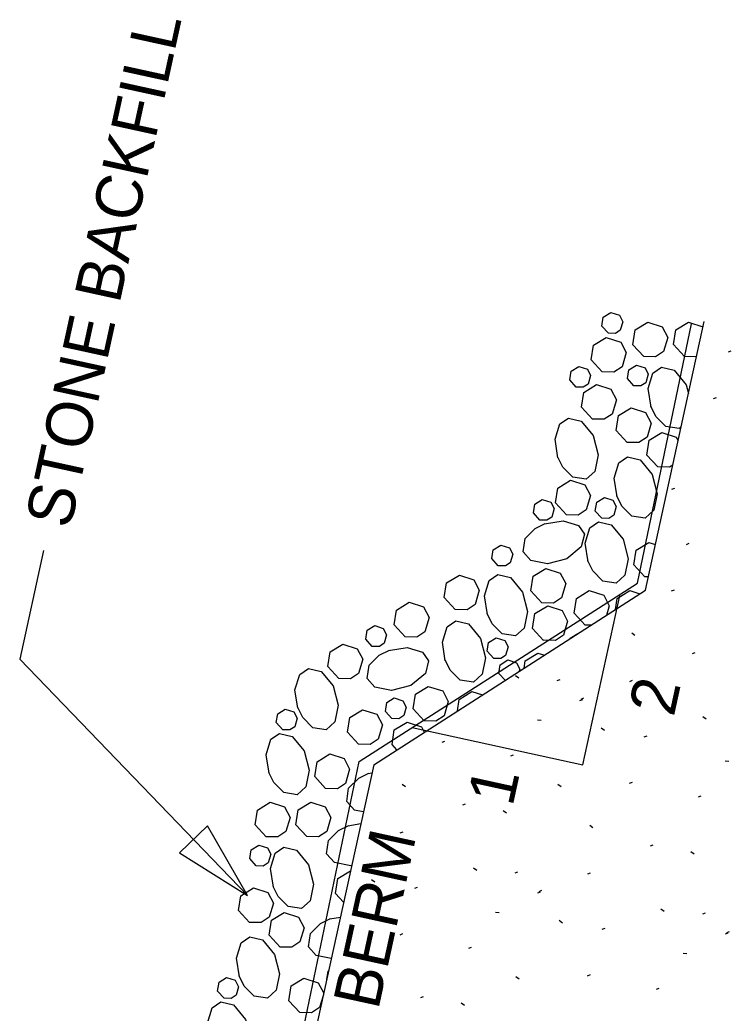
# Model space of a CAD drawing. Extents: x 2126110 to 2128246, y 1804858 to 1811658.
# Drawn here: x 2126594.3 to 2126671.1, y 1805662.4 to 1805769.7 of the extents above; entities that cross this region are included whole.
import ezdxf

# ---------------------------------------------------------------- set-up
doc = ezdxf.new("R2010")
doc.units = 0
doc.layers.add('1', color=7, linetype='Continuous')

msp = doc.modelspace()

# ---------------------------------------------------------------- linework, layer by layer
at = {"layer": '1'}
for p, q in [((2126661.04, 1805708.83), (2126666.87, 1805736.83)), ((2126661.88, 1805708.05), (2126668.22, 1805737.07)), ((2126670.84, 1805733.79), (2126671.14, 1805733.91)), ((2126669.25, 1805728.77), (2126669.55, 1805728.89)), ((2126664.74, 1805718.99), (2126665.04, 1805719.1)), ((2126666.3, 1805713.01), (2126666.6, 1805713.13)), ((2126596.85, 1805712.34), (2126594.29, 1805700.61)), ((2126662.19, 1805709.49), (2126661.81, 1805709.5)), ((2126630.94, 1805689.55), (2126661.04, 1805708.83)), ((2126632.52, 1805689.22), (2126661.88, 1805708.05)), ((2126655.12, 1805689.19), (2126659.15, 1805707.63)), ((2126664.71, 1805707.99), (2126665.01, 1805708.11)), ((2126655.99, 1805704.28), (2126655.37, 1805704.29)), ((2126660.75, 1805703.18), (2126660.4, 1805703.43)), ((2126666.95, 1805701.22), (2126667.25, 1805701.33)), ((2126618.9, 1805675.08), (2126594.29, 1805700.61)), ((2126648.19, 1805698.56), (2126647.84, 1805698.82)), ((2126652.35, 1805698.31), (2126652.65, 1805698.43)), ((2126660.2, 1805698.21), (2126660.5, 1805698.33)), ((2126654.94, 1805696.31), (2126655.24, 1805696.43)), ((2126654.8, 1805696.16), (2126655.1, 1805696.27)), ((2126668.46, 1805694.13), (2126668.1, 1805694.39)), ((2126636.67, 1805693.22), (2126655.12, 1805689.19)), ((2126650.21, 1805694.06), (2126650.61, 1805694.02)), ((2126657.46, 1805692.9), (2126657.11, 1805693.15)), ((2126661.76, 1805692.24), (2126662.06, 1805692.35)), ((2126639.91, 1805691.64), (2126640.21, 1805691.76)), ((2126647.35, 1805690.19), (2126647.64, 1805690.3)), ((2126624.81, 1805660.2), (2126630.94, 1805689.55)), ((2126632.52, 1805689.22), (2126626.17, 1805660.17)), ((2126670.48, 1805689.63), (2126670.88, 1805689.59)), ((2126631.91, 1805688.27), (2126632.33, 1805688.34)), ((2126635.95, 1805686.82), (2126635.6, 1805687.08)), ((2126652.77, 1805686.83), (2126652.41, 1805687.09)), ((2126660.17, 1805687.21), (2126660.47, 1805687.33)), ((2126667.61, 1805685.76), (2126667.91, 1805685.87)), ((2126642.15, 1805684.87), (2126642.45, 1805684.98)), ((2126646.87, 1805683.98), (2126646.52, 1805684.24)), ((2126629.74, 1805682.63), (2126631.13, 1805682.86)), ((2126656.21, 1805682.4), (2126655.86, 1805682.66)), ((2126635.39, 1805681.86), (2126635.69, 1805681.98)), ((2126662.41, 1805680.44), (2126662.71, 1805680.55)), ((2126667.13, 1805679.56), (2126666.78, 1805679.81)), ((2126643.65, 1805677.78), (2126643.3, 1805678.04)), ((2126647.81, 1805677.53), (2126648.11, 1805677.65)), ((2126655.66, 1805677.43), (2126655.96, 1805677.55)), ((2126632.66, 1805676.54), (2126632.3, 1805676.8)), ((2126636.96, 1805675.89), (2126637.26, 1805676)), ((2126650.26, 1805675.38), (2126650.56, 1805675.5)), ((2126650.4, 1805675.53), (2126650.7, 1805675.65)), ((2126627.79, 1805672.56), (2126628.92, 1805672.75)), ((2126645.67, 1805673.28), (2126646.07, 1805673.24)), ((2126663.91, 1805673.35), (2126663.56, 1805673.61)), ((2126668.07, 1805673.1), (2126668.37, 1805673.22)), ((2126652.92, 1805672.12), (2126652.57, 1805672.38)), ((2126635.37, 1805670.86), (2126635.67, 1805670.98)), ((2126657.22, 1805671.46), (2126657.52, 1805671.57)), ((2126670.53, 1805670.95), (2126670.82, 1805671.07)), ((2126670.66, 1805671.1), (2126670.96, 1805671.22)), ((2126642.81, 1805669.41), (2126643.1, 1805669.52)), ((2126665.94, 1805668.85), (2126666.34, 1805668.81)), ((2126631.41, 1805666.05), (2126631.06, 1805666.31)), ((2126648.23, 1805666.05), (2126647.87, 1805666.31)), ((2126655.63, 1805666.43), (2126655.93, 1805666.55)), ((2126637.61, 1805664.09), (2126637.91, 1805664.2)), ((2126663.07, 1805664.98), (2126663.37, 1805665.1)), ((2126642.33, 1805663.21), (2126641.98, 1805663.46))]:
    msp.add_line(p, q, dxfattribs=at)
for points in [[(2126657.88, 1805735.82), (2126657.17, 1805736.59), (2126657.32, 1805737.55), (2126658.14, 1805738.05), (2126659.07, 1805737.75), (2126659.43, 1805737.06), (2126659.16, 1805736.14), (2126658.64, 1805735.8), (2126657.88, 1805735.82)], [(2126661.71, 1805733.29), (2126660.52, 1805734.58), (2126660.78, 1805736.17), (2126662.15, 1805737.01), (2126663.7, 1805736.51), (2126664.3, 1805735.36), (2126663.85, 1805733.83), (2126662.98, 1805733.26), (2126661.71, 1805733.29)], [(2126666.11, 1805733.3), (2126664.92, 1805734.59), (2126665.17, 1805736.18), (2126666.55, 1805737.02), (2126668.1, 1805736.52), (2126668.1, 1805736.52)], [(2126657.21, 1805731.64), (2126656.03, 1805732.93), (2126656.28, 1805734.52), (2126657.65, 1805735.37), (2126659.21, 1805734.86), (2126659.8, 1805733.72), (2126659.35, 1805732.19), (2126658.48, 1805731.61), (2126657.21, 1805731.64)], [(2126667.39, 1805733.28), (2126667.38, 1805733.27), (2126666.11, 1805733.3)], [(2126654.41, 1805729.99), (2126653.7, 1805730.77), (2126653.85, 1805731.72), (2126654.67, 1805732.23), (2126655.61, 1805731.93), (2126655.96, 1805731.24), (2126655.69, 1805730.32), (2126655.17, 1805729.98), (2126654.41, 1805729.99)], [(2126660.64, 1805730.14), (2126659.93, 1805730.91), (2126660.08, 1805731.87), (2126660.9, 1805732.37), (2126661.84, 1805732.07), (2126662.19, 1805731.38), (2126661.92, 1805730.46), (2126661.4, 1805730.12), (2126660.64, 1805730.14)], [(2126662.49, 1805727.84), (2126662.16, 1805729.85), (2126662.68, 1805731.51), (2126663.62, 1805732.14), (2126664.99, 1805731.82), (2126666.28, 1805730.26), (2126666.52, 1805729.3)], [(2126656.16, 1805726.54), (2126654.97, 1805727.84), (2126655.23, 1805729.43), (2126656.6, 1805730.27), (2126658.15, 1805729.77), (2126658.75, 1805728.62), (2126658.3, 1805727.09), (2126657.43, 1805726.52), (2126656.16, 1805726.55)], [(2126659.91, 1805724.03), (2126658.72, 1805725.32), (2126658.98, 1805726.92), (2126660.35, 1805727.76), (2126661.9, 1805727.26), (2126662.5, 1805726.11), (2126662.05, 1805724.58), (2126661.18, 1805724), (2126659.91, 1805724.03)], [(2126665.74, 1805725.73), (2126665.53, 1805725.53), (2126664.09, 1805725.75), (2126663, 1805726.84), (2126662.46, 1805727.93)], [(2126652.43, 1805722.36), (2126652.11, 1805724.36), (2126652.62, 1805726.02), (2126653.56, 1805726.66), (2126654.93, 1805726.33), (2126656.23, 1805724.77), (2126656.76, 1805722.68), (2126656.4, 1805720.89), (2126655.47, 1805720.05), (2126654.03, 1805720.26), (2126652.94, 1805721.35), (2126652.4, 1805722.44)], [(2126663.21, 1805721.37), (2126662.02, 1805722.66), (2126662.28, 1805724.25), (2126663.65, 1805725.1), (2126665.21, 1805724.59), (2126665.41, 1805724.2)], [(2126658.81, 1805718.16), (2126658.49, 1805720.16), (2126659, 1805721.82), (2126659.94, 1805722.46), (2126661.31, 1805722.13), (2126662.6, 1805720.57), (2126663.14, 1805718.48), (2126662.78, 1805716.69), (2126661.85, 1805715.84), (2126660.41, 1805716.06), (2126659.32, 1805717.15), (2126658.78, 1805718.24)], [(2126664.83, 1805721.57), (2126664.48, 1805721.34), (2126663.21, 1805721.37)], [(2126653.35, 1805716.2), (2126652.17, 1805717.5), (2126652.42, 1805719.09), (2126653.79, 1805719.93), (2126655.35, 1805719.43), (2126655.94, 1805718.28), (2126655.49, 1805716.75), (2126654.62, 1805716.18), (2126653.35, 1805716.21)], [(2126650.48, 1805715.64), (2126649.77, 1805716.41), (2126649.92, 1805717.37), (2126650.74, 1805717.87), (2126651.67, 1805717.57), (2126652.03, 1805716.88), (2126651.76, 1805715.96), (2126651.24, 1805715.62), (2126650.48, 1805715.64)], [(2126657.18, 1805715.84), (2126656.46, 1805716.61), (2126656.62, 1805717.57), (2126657.44, 1805718.08), (2126658.37, 1805717.77), (2126658.73, 1805717.09), (2126658.46, 1805716.17), (2126657.94, 1805715.82), (2126657.18, 1805715.84)], [(2126650.98, 1805715.24), (2126652.98, 1805715.56), (2126654.64, 1805715.05), (2126655.28, 1805714.11), (2126654.95, 1805712.74), (2126653.39, 1805711.44), (2126651.3, 1805710.91), (2126649.51, 1805711.27), (2126648.66, 1805712.2), (2126648.88, 1805713.64), (2126649.97, 1805714.73), (2126651.06, 1805715.27)], [(2126655.7, 1805711.14), (2126655.37, 1805713.15), (2126655.88, 1805714.81), (2126656.82, 1805715.45), (2126658.19, 1805715.12), (2126659.49, 1805713.56), (2126660.02, 1805711.46), (2126659.66, 1805709.68), (2126658.73, 1805708.83), (2126657.29, 1805709.05), (2126656.2, 1805710.14), (2126655.66, 1805711.23)], [(2126645.98, 1805710.7), (2126645.27, 1805711.48), (2126645.42, 1805712.43), (2126646.25, 1805712.94), (2126647.18, 1805712.64), (2126647.54, 1805711.95), (2126647.27, 1805711.03), (2126646.75, 1805710.68), (2126645.98, 1805710.7)], [(2126661.8, 1805709.5), (2126660.62, 1805710.79), (2126660.87, 1805712.38), (2126662.24, 1805713.23), (2126662.96, 1805712.99)], [(2126650.68, 1805706.69), (2126649.5, 1805707.98), (2126649.75, 1805709.57), (2126651.12, 1805710.42), (2126652.68, 1805709.91), (2126653.27, 1805708.77), (2126652.82, 1805707.24), (2126651.95, 1805706.66), (2126650.68, 1805706.69)], [(2126641.34, 1805705.97), (2126640.15, 1805707.26), (2126640.4, 1805708.85), (2126641.78, 1805709.7), (2126643.33, 1805709.19), (2126643.93, 1805708.05), (2126643.48, 1805706.52), (2126642.61, 1805705.94), (2126641.34, 1805705.97)], [(2126644.81, 1805705.44), (2126644.48, 1805707.45), (2126644.99, 1805709.11), (2126645.93, 1805709.75), (2126647.3, 1805709.42), (2126648.6, 1805707.86), (2126649.13, 1805705.76), (2126648.77, 1805703.98), (2126647.84, 1805703.13), (2126646.4, 1805703.35), (2126645.31, 1805704.44), (2126644.77, 1805705.53)], [(2126655.37, 1805704.29), (2126654.18, 1805705.58), (2126654.44, 1805707.17), (2126655.81, 1805708.02), (2126657.37, 1805707.51), (2126657.96, 1805706.36), (2126657.66, 1805705.34)], [(2126658.64, 1805705.98), (2126658.84, 1805707.18), (2126660.21, 1805708.03), (2126661.29, 1805707.68)], [(2126635.91, 1805703.03), (2126634.72, 1805704.32), (2126634.97, 1805705.91), (2126636.35, 1805706.76), (2126637.9, 1805706.25), (2126638.5, 1805705.1), (2126638.05, 1805703.57), (2126637.18, 1805703), (2126635.91, 1805703.03)], [(2126650.87, 1805702.64), (2126649.69, 1805703.94), (2126649.94, 1805705.53), (2126651.32, 1805706.37), (2126652.87, 1805705.87), (2126653.47, 1805704.72), (2126653.01, 1805703.19), (2126652.15, 1805702.62), (2126650.88, 1805702.65)], [(2126632.37, 1805702), (2126631.66, 1805702.77), (2126631.81, 1805703.73), (2126632.63, 1805704.24), (2126633.56, 1805703.93), (2126633.92, 1805703.24), (2126633.65, 1805702.33), (2126633.13, 1805701.98), (2126632.37, 1805702)], [(2126640.26, 1805700.45), (2126639.94, 1805702.45), (2126640.45, 1805704.11), (2126641.39, 1805704.75), (2126642.76, 1805704.42), (2126644.06, 1805702.86), (2126644.59, 1805700.77), (2126644.23, 1805698.98), (2126643.3, 1805698.13), (2126641.86, 1805698.35), (2126640.77, 1805699.44), (2126640.23, 1805700.53)], [(2126645.49, 1805700.69), (2126644.78, 1805701.47), (2126644.93, 1805702.42), (2126645.76, 1805702.93), (2126646.69, 1805702.63), (2126647.05, 1805701.94), (2126646.77, 1805701.02), (2126646.25, 1805700.68), (2126645.49, 1805700.69)], [(2126653.74, 1805702.83), (2126653.74, 1805702.87), (2126654.57, 1805703.38), (2126654.58, 1805703.37)], [(2126628.74, 1805698.52), (2126627.55, 1805699.81), (2126627.81, 1805701.4), (2126629.18, 1805702.25), (2126630.73, 1805701.74), (2126631.33, 1805700.6), (2126630.88, 1805699.07), (2126630.01, 1805698.49), (2126628.74, 1805698.52)], [(2126634.13, 1805701.56), (2126636.13, 1805701.89), (2126637.79, 1805701.37), (2126638.43, 1805700.43), (2126638.1, 1805699.06), (2126636.54, 1805697.77), (2126634.45, 1805697.24), (2126632.66, 1805697.59), (2126631.81, 1805698.52), (2126632.03, 1805699.96), (2126633.12, 1805701.05), (2126634.21, 1805701.59)], [(2126648.76, 1805699.64), (2126648.89, 1805700.43), (2126650.26, 1805701.28), (2126650.96, 1805701.05)], [(2126624.34, 1805695.31), (2126624.01, 1805697.31), (2126624.53, 1805698.97), (2126625.47, 1805699.61), (2126626.84, 1805699.28), (2126628.13, 1805697.72), (2126628.67, 1805695.63), (2126628.31, 1805693.84), (2126627.38, 1805693), (2126625.94, 1805693.21), (2126624.85, 1805694.3), (2126624.31, 1805695.39)], [(2126646.72, 1805698.33), (2126646.04, 1805699.06), (2126646.2, 1805700.02), (2126647.02, 1805700.53), (2126647.95, 1805700.22), (2126648.31, 1805699.53), (2126648.24, 1805699.31)], [(2126637.98, 1805693.95), (2126636.8, 1805695.25), (2126637.05, 1805696.84), (2126638.42, 1805697.68), (2126639.98, 1805697.18), (2126640.57, 1805696.03), (2126640.12, 1805694.5), (2126639.25, 1805693.93), (2126637.98, 1805693.95)], [(2126634.49, 1805694.19), (2126633.78, 1805694.97), (2126633.93, 1805695.92), (2126634.75, 1805696.43), (2126635.68, 1805696.13), (2126636.04, 1805695.44), (2126635.77, 1805694.52), (2126635.25, 1805694.18), (2126634.49, 1805694.19)], [(2126641.56, 1805695.02), (2126641.76, 1805696.27), (2126643.13, 1805697.11), (2126644.26, 1805696.75)], [(2126622.71, 1805692.99), (2126621.99, 1805693.77), (2126622.15, 1805694.72), (2126622.97, 1805695.23), (2126623.9, 1805694.93), (2126624.26, 1805694.24), (2126623.99, 1805693.32), (2126623.47, 1805692.97), (2126622.71, 1805692.99)], [(2126630.88, 1805691.43), (2126629.69, 1805692.73), (2126629.94, 1805694.32), (2126631.32, 1805695.16), (2126632.87, 1805694.66), (2126633.47, 1805693.51), (2126633.01, 1805691.98), (2126632.15, 1805691.41), (2126630.88, 1805691.44)], [(2126635.02, 1805690.82), (2126634.5, 1805691.39), (2126634.75, 1805692.98), (2126636.12, 1805693.82), (2126637.68, 1805693.32), (2126637.98, 1805692.73)], [(2126621.22, 1805688.3), (2126620.9, 1805690.3), (2126621.41, 1805691.96), (2126622.35, 1805692.6), (2126623.72, 1805692.27), (2126625.02, 1805690.71), (2126625.55, 1805688.62), (2126625.19, 1805686.83), (2126624.26, 1805685.98), (2126622.82, 1805686.2), (2126621.73, 1805687.29), (2126621.19, 1805688.38)], [(2126627.33, 1805686.65), (2126626.15, 1805687.94), (2126626.4, 1805689.53), (2126627.77, 1805690.38), (2126629.33, 1805689.87), (2126629.92, 1805688.73), (2126629.47, 1805687.2), (2126628.6, 1805686.62), (2126627.33, 1805686.65)], [(2126631.4, 1805684.12), (2126630.44, 1805684.31), (2126629.6, 1805685.24), (2126629.81, 1805686.68), (2126630.9, 1805687.77), (2126631.99, 1805688.31)], [(2126620.9, 1805681.44), (2126619.71, 1805682.73), (2126619.97, 1805684.32), (2126621.34, 1805685.17), (2126622.89, 1805684.66), (2126623.49, 1805683.52), (2126623.04, 1805681.99), (2126622.17, 1805681.41), (2126620.9, 1805681.44)], [(2126625.3, 1805681.45), (2126624.11, 1805682.74), (2126624.37, 1805684.33), (2126625.74, 1805685.18), (2126627.29, 1805684.67), (2126627.89, 1805683.53), (2126627.44, 1805682), (2126626.57, 1805681.42), (2126625.3, 1805681.45)], [(2126630.14, 1805678.33), (2126630.06, 1805678.31), (2126628.27, 1805678.66), (2126627.43, 1805679.59), (2126627.64, 1805681.03), (2126628.73, 1805682.12), (2126629.82, 1805682.66)], [(2126619.83, 1805678.29), (2126619.12, 1805679.07), (2126619.27, 1805680.02), (2126620.1, 1805680.53), (2126621.03, 1805680.23), (2126621.39, 1805679.54), (2126621.11, 1805678.62), (2126620.59, 1805678.27), (2126619.83, 1805678.29)], [(2126621.68, 1805676), (2126621.36, 1805678), (2126621.87, 1805679.66), (2126622.81, 1805680.3), (2126624.18, 1805679.97), (2126625.47, 1805678.41), (2126626.01, 1805676.32), (2126625.65, 1805674.53), (2126624.72, 1805673.69), (2126623.28, 1805673.9), (2126622.19, 1805674.99), (2126621.65, 1805676.08)], [(2126629.27, 1805674.36), (2126628.38, 1805675.32), (2126628.64, 1805676.91), (2126630.01, 1805677.76), (2126630.01, 1805677.76)], [(2126619.1, 1805672.19), (2126617.92, 1805673.48), (2126618.17, 1805675.07), (2126619.54, 1805675.92), (2126621.1, 1805675.41), (2126621.69, 1805674.26), (2126621.24, 1805672.74), (2126620.37, 1805672.16), (2126619.1, 1805672.19)], [(2126622.4, 1805669.52), (2126621.22, 1805670.82), (2126621.47, 1805672.41), (2126622.84, 1805673.25), (2126624.4, 1805672.75), (2126624.99, 1805671.6), (2126624.54, 1805670.07), (2126623.67, 1805669.5), (2126622.4, 1805669.52)], [(2126627.94, 1805668.27), (2126626.32, 1805668.6), (2126625.48, 1805669.53), (2126625.69, 1805670.97), (2126626.78, 1805672.06), (2126627.87, 1805672.59)], [(2126618.01, 1805666.31), (2126617.68, 1805668.31), (2126618.19, 1805669.98), (2126619.13, 1805670.61), (2126620.5, 1805670.29), (2126621.8, 1805668.72), (2126622.33, 1805666.63), (2126621.97, 1805664.85), (2126621.04, 1805664), (2126619.6, 1805664.21), (2126618.51, 1805665.3), (2126617.97, 1805666.4)], [(2126627.45, 1805666.02), (2126627.59, 1805666.93), (2126627.65, 1805666.96)], [(2126616.37, 1805663.99), (2126615.66, 1805664.77), (2126615.81, 1805665.73), (2126616.63, 1805666.23), (2126617.57, 1805665.93), (2126617.92, 1805665.24), (2126617.65, 1805664.32), (2126617.13, 1805663.98), (2126616.37, 1805664)], [(2126624.54, 1805662.44), (2126623.35, 1805663.73), (2126623.61, 1805665.32), (2126624.98, 1805666.17), (2126626.53, 1805665.66), (2126627.12, 1805664.53)], [(2126627.08, 1805664.36), (2126626.68, 1805662.99), (2126625.81, 1805662.41), (2126624.54, 1805662.44)], [(2126614.89, 1805659.3), (2126614.56, 1805661.3), (2126615.08, 1805662.96), (2126616.02, 1805663.6), (2126617.39, 1805663.28), (2126618.68, 1805661.71), (2126619.21, 1805659.62), (2126618.85, 1805657.83), (2126617.92, 1805656.99), (2126616.49, 1805657.2), (2126615.4, 1805658.29), (2126614.86, 1805659.39)]]:
    msp.add_lwpolyline(points, dxfattribs=at)
msp.add_lwpolyline([(2126611.53, 1805679.69), (2126618.9, 1805675.08), (2126614.56, 1805682.62)], close=True, dxfattribs=at)

# ---------------------------------------------------------------- texts
for s, p in [('STONE BACKFILL', (2126599.73, 1805714.58)), ('2', (2126664.93, 1805694.29)), ('1', (2126647.51, 1805684.59)), ('BERM', (2126633, 1805662.63))]:
    msp.add_text(s, height=5, rotation=77.6736, dxfattribs=at).set_placement(p)

doc.saveas('drawing.dxf')
